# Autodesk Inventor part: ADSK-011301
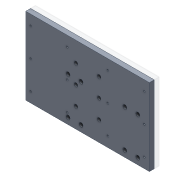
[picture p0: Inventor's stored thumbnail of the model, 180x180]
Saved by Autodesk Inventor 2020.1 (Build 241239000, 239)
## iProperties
Created: 1999-11
Part Number: ADSK-011301
Material: Pearson Aluminium
Document SubType Name: Modeling
Designer: sspink
Density: 2.71 g/cm^3
Appearance: Pearson-Aluminum
Mass: 1837.99 g
Surface Area: 1321.59 cm^2
Volume: 678.225 cm^3
Control State: 0
Master: False
Checked Out: False
Shininess: 35.0
Length Units: 11269
Angle Units: 11279
Time Units: 11290
Mass Units: 11283
Length Display Precision: 3
Angle Display Precision: 2
Compacted: True
Cutlength: 12 *
Material Desc: FLAT,ALUM,0.500 X 8.00
Material_number: A084017
Dimensions: 305x190x12 mm
Mass: 1,838 kg
DocNumber: ADSK-011301.ipt
Folder: 01 - Themengebiete\Simplification\01 - Packaging machine\
VDS_Category: 3D Komponenten
Density: 2.71
Volumn: 717.0795579328652
Area: 1337.2459339185411
PropertySet Name: Model Information
Author: sspink
Revision Number: -
Title: base plate
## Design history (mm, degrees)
node "Extrusion1" dims "d2" = 12, "d3" = 0
  sketch "Sketch1"
    geometry: L1 (-152.5, 95)-(152.5, 95); L2 (152.5, 95)-(152.5, -95); L3 (152.5, -95)-(-152.5, -95); L4 (-152.5, -95)-(-152.5, 95); 3 further points
    constraints: 8 end point, 2 midpoint, 2 parallel, 1 horizontal, 1 horizontal alignment, 1 perpendicular, 1 vertical alignment
    dimensions: "d0" = 305 distance of L1.start L1.end; "d1" = 190 distance of L3.end L1.start
node "Hole2" dims "d18" = 4.5, "d19" = 9.525, "d20" = 6.35, "d21" = 60 deg, "d22" = 19.05, "d23" = 118 deg, "d71" = 6
  sketch "Sketch3"
    geometry: L1 (-152.5, -95)-(-152.5, 95) reference; L2 (-140, 70)-(-50, 70); L3 (-50, 70)-(-50, -70); L4 (-50, -70)-(-140, -70); L5 (-140, -70)-(-140, 70); L6 (-152.5, 95)-(152.5, 95) reference; L7 (152.5, -95)-(-152.5, -95) reference; L8 (0, 133)-(0, -133) reference; L9 (-95, 70)-(-95, -70); 3 further points
    constraints: 10 end point, 5 midpoint, 2 parallel, 1 horizontal, 1 horizontal alignment, 1 perpendicular
    dimensions: "d69" = 90 distance of L2.start L2.end; "d70" = 140 distance between parallel lines of L2 L4; "d76" = 95 distance between parallel lines of L9 L8
workplane "Arbeitsebene2"
mirror "Spiegeln1"
workplane "Work Plane1"
node "Hole4" dims "d49" = 9, "d50" = 19, "d51" = 6.35, "d52" = 90 deg, "d53" = 19.05, "d54" = 118 deg, "d77" = 6
  sketch "Sketch5"
    geometry: L1 (-28.5, 46)-(-28.5, -46); L2 (28.5, 46)-(28.5, -46); L3 (-28.5, 0)-(28.5, 0); 2 further points
    constraints: 6 end point, 3 midpoint, 2 horizontal alignment, 2 vertical alignment, 1 coincident, 1 horizontal
    dimensions: "d67" = 57 distance of L2.end L1.end; "d68" = 92 distance of L1.start L1.end
node "Hole5" dims "d61" = 9.906, "d62" = 9.525, "d63" = 6.35, "d64" = 60 deg, "d65" = 19.05, "d66" = 118 deg
  sketch "Sketch6"
    geometry: L1 (152.5, -95)-(-152.5, -95) reference; L2 (152.5, 95)-(152.5, -95) reference; L3 (92, 16.25)-(124, 16.25); L4 (124, 16.25)-(124, -79.25); L5 (124, -79.25)-(92, -79.25); L6 (92, -79.25)-(92, 16.25); L7 (-48, 16.25)-(-16, 16.25); L8 (-16, 16.25)-(-16, -79.25); L9 (-16, -79.25)-(-48, -79.25); L10 (-48, -79.25)-(-48, 16.25); 4 further points
    constraints: 16 end point, 6 horizontal alignment, 4 parallel, 4 vertical alignment, 2 horizontal, 2 perpendicular
    dimensions: "d55" = 28.5 distance from line of L4.end L2; "d57" = 15.75 distance from line of L4.end L1; "d72" = 108 distance between parallel lines of L8 L6; "d73" = 32 distance of L3.start L3.end; "d74" = 32 distance of L7.start L7.end (= d73); "d79" = 95.5 distance of point (124, 16.25) L4.end
node "Solide1"
node "Corps solides"
node "Corps surfaciques"
workplane "Arbeitsebene3"
other parameters: "d14" = 12.7, "d15" = 25.4, "d44" = 152.4, "d78" = 90 deg
